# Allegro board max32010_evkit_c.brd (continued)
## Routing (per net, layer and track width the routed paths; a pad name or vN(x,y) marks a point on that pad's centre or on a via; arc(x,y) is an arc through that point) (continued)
UNNAMED_1_RESSMD_I39_2: length 3.8
  TOP w0.356: U1.6 40.71,22.92 41.17,22.45 R4.2
  TOP w0.762: R4.2 43.76,22.45 R5.1
UNNAMED_2_CAPNP_I3_2: length 3.9
  TOP w0.254: R10.2 C13.2 118.24,21.34 118.36,21.46 U4.2
UNNAMED_2_CAPNP_I7_2: length 2.6
  TOP w0.254: U4.1 117.09,22.07 116.84,21.82 C17.2
UNNAMED_2_CAPNP_I18_2: length 2.6
  TOP w0.254: C19.2 116.84,39.6 117.09,39.85 U5.1
UNNAMED_2_CAPNP_I19_2: length 3.9
  TOP w0.254: U5.2 118.36,39.24 118.24,39.12 C14.2 R12.2
UNNAMED_2_CAPNP_I33_2: length 2.8
  TOP w0.254: U7.1 117.13,75.48 116.08,74.42 C23.2
UNNAMED_2_CAPNP_I35_2: length 3.9
  TOP w0.254: U7.2 117.78,75.37 117.47,75.06 C16.2 R16.2
UNNAMED_2_CAPNP_I44_2: length 2.8
  TOP w0.254: C21.2 116.08,56.64 117.13,57.7 U6.1
UNNAMED_2_CAPNP_I46_2: length 3.9
  TOP w0.254: U6.2 117.78,57.59 117.47,57.28 C15.2 R14.2
UNNAMED_2_MAX5322_I51_CLR: length 2.6
  TOP w0.254: U8.6 130.85,19.54 R18.2
UNNAMED_2_MAX5322_I51_SHDN: length 2.5
  TOP w0.254: R19.2 129.55,19.47 U8.4
UNNAMED_2_MAX5322_I73_CLR: length 2.6
  TOP w0.254: R20.2 130.85,37.32 U9.6
UNNAMED_2_MAX5322_I73_SHDN: length 2.5
  TOP w0.254: R21.2 129.55,37.25 U9.4
UNNAMED_2_MAX5322_I92_CLR: length 2.3
  TOP w0.254: U10.6 130.85,55.36 R22.2
UNNAMED_2_MAX5322_I92_SHDN: length 2.3
  TOP w0.254: U10.4 129.55,56.09 129.54,56.08 R23.2
UNNAMED_2_MAX5322_I111_CLR: length 2.6
  TOP w0.254: R24.2 130.85,72.88 U11.6
UNNAMED_2_MAX5322_I111_SHDN: length 2.5
  TOP w0.254: R25.2 129.55,72.81 U11.4
UNNAMED_2_MAX6126_I1_GNDS: length 2.5
  TOP w0.254: R11.1 121.03,21.34 120.9,21.46 U4.4
UNNAMED_2_MAX6126_I13_GNDS: length 2.5
  TOP w0.254: U5.4 120.9,39.24 121.03,39.12 R13.1
UNNAMED_2_MAX6126_I25_GNDS: length 2.9
  TOP w0.254: U6.4 119.09,57.57 120.24,56.41 R15.1
UNNAMED_2_MAX6126_I50_GNDS: length 2.9
  TOP w0.254: R17.1 120.24,74.19 119.09,75.35 U7.4
UNNAMED_2_MAX44245_I130_INA: length 6
  TOP w0.254: R57.2 R59.1 144.06,27.41 144.37,27.72 U14.2
UNNAMED_2_MAX44245_I131_INB: length 6
  TOP w0.254: U14.6 146.97,27.72 147.28,27.41 R58.1 R56.2
UNNAMED_2_MAX44245_I132_INC: length 5.9
  TOP w0.254: R60.2 R62.1 147.35,41.17 146.97,40.8 U14.9
UNNAMED_2_MAX44245_I133_IND: length 5.8
  TOP w0.254: R61.2 R63.1 143.87,41.17 144.37,40.67 U14.13
UNNAMED_5_CAPNP_I49_1: length 19.1
  TOP w0.254: U12.23 68.5,40.47 76.2,32.77 C62.1
UNNAMED_5_CAPNP_I51_1: length 19.5
  TOP w0.254: U12.24 69,40.98 77.6,32.38 C61.1
UNNAMED_5_CAPNP_I147_1: length 20.4
  TOP w0.254: U12.69 60.5,68.28 56.39,72.39 56.39,77.62 56.64,77.88 C60.1
UNNAMED_5_CAPNP_I147_2: length 18.1
  TOP w0.254: C60.2 57.15,72.64 61,68.79 U12.68
UNNAMED_5_CAPNP_I155_2: length 2.2
  TOP w0.254: U15.6 141.18,97.61 C68.2
UNNAMED_5_CAPNP_I158_2: length 3.8
  TOP w0.356: C67.2 147.07,97.43 146.89,97.61 U15.3 144.6,97.61 U15.9
UNNAMED_5_CAPNP_I169_2: length 3.1
  TOP w0.356: C75.2 106.68,53.72 106,53.05 U16.17
UNNAMED_5_CAPNP_I171_2: length 2.8
  TOP w0.356: U16.16 106.71,52.4 C74.2
UNNAMED_5_EKMAX32010_I1_21: length 29.2
  TOP w0.254: U12.21 67.5,40.45 75.44,32.51 75.44,25.1 78.69,21.84 VRXP.1
UNNAMED_5_EKMAX32010_I1_40: length 21
  TOP w0.254: EXTSEL.1 79.76,56.39 76.44,53.07 U12.40
UNNAMED_5_EKMAX32010_I1_41: length 21.9
  TOP w0.254: U12.41 73.38,53.57 v1(73.91,54.1) 74.8,54.1 80.26,59.56 HITEMP.1
  BOTTOM w0.254: v1(73.91,54.1) R47.2 R45.2
UNNAMED_5_EKMAX32010_I1_42: length 25.7
  TOP w0.254: ILIMLO.1 80.52,62.1 v1(73.91,55.5) 72.48,54.07 U12.42
  BOTTOM w0.254: v1(73.91,55.5) R43.2 R44.2
UNNAMED_5_EKMAX32010_I1_43: length 24.8
  TOP w0.254: U12.43 72.08,54.57 73.96,56.46 v1(73.96,58.29) 80.31,64.64 ILIMHI.1
  BOTTOM w0.254: R42.2 R41.2 v1(73.96,58.29)
UNNAMED_5_HEADER2P_I37_2: length 42.4
  TOP w0.254: U12.15 v1(64.5,42.93)
  BOTTOM w0.254: J1.2 55.75,16.76 52.45,20.07 52.45,37.59 58.42,43.56 62.61,43.56 63.25,42.93 v1(64.5,42.93)
UNNAMED_5_HEADER2P_I38_2: length 33
  TOP w0.254: U12.16 65,43.31 65.12,43.18 65.12,41.94 74.8,32.26 74.8,24.89 77.98,21.72 J2.2
UNNAMED_5_HEADER2P_I71_1: length 31.1
  TOP w0.254: J3.1 87.6,51.84 R30.1 ; J3.1 87.6,50.27 R29.2 ; J3.1 81.28,51.05 81.26,51.07 U12.36
  BOTTOM w0.254: VTHR.1 89.03,46.35 88.39,46.99 J3.1
UNNAMED_5_HEADER2P_I160_1: length 110.4
  TOP w0.254: v1(147.07,98.55) 146.77,98.26 U15.4 ; v1(138.56,34.04) J6.1
  BOTTOM w0.254: v1(147.07,98.55) 138.56,90.04 v1(138.56,34.04)
UNNAMED_5_LED_I57_B: length 1.7
  BOTTOM w0.254: R50.1 76.48,42.6 76.59,42.48 DS5.K
UNNAMED_5_LED_I62_B: length 1.7
  BOTTOM w0.254: R48.1 76.48,48.41 76.59,48.53 DS4.K
UNNAMED_5_LED_I83_B: length 25.7
  TOP w0.254: v1(91.57,70.99) 92.2,71.63 DS3.K
  BOTTOM w0.254: R47.1 77.34,54.1 79.88,56.64 79.88,59.31 v1(91.57,70.99)
UNNAMED_5_LED_I91_B: length 25.9
  TOP w0.254: v1(91.69,73.79) 92.32,73.79 92.44,73.91 DS2.K
  BOTTOM w0.254: v1(91.69,73.79) 91.69,72 79.12,59.43 79.12,57.78 78.36,57.02 R44.1
UNNAMED_5_LED_I97_B: length 26
  TOP w0.254: DS1.K v1(91.06,76.2)
  BOTTOM w0.254: R42.1 78.76,59.82 91.06,72.11 v1(91.06,76.2)
VDAC1: length 8.7
  TOP w0.381: U8.21 v1(132.15,27.18) ; U9.21 v1(132.15,44.96)
  BOTTOM w0.508: v1(132.15,27.18) 132.11,27.22 C38.2 C26.2 ; v1(132.15,44.96) 132.11,45 C41.2 C29.2
VDAC2: length 8.7
  TOP w0.381: U10.21 v1(132.15,62.74) ; U11.21 v1(132.15,80.52)
  BOTTOM w0.508: C32.2 C44.2 132.11,62.78 v1(132.15,62.74) ; C35.2 C47.2 132.11,80.56 v1(132.15,80.52)
  vias: v1(40.26,18.92) v1(41.27,18.92) v1(41.27,18.03) v1(110.24,14.1) v1(110.24,12.95) v1(112.01,14.1) v1(112.01,12.95) v1(113.67,14.1) v1(113.67,12.95) v1(115.32,14.1) v1(115.32,12.95)
VL: length 25.2
  TOP w0.254: v1(72.74,51.79) 72.52,51.57 U12.37
  TOP w0.356: U16.14 105.21,51.09 106.78,49.53 C71.2
  TOP w0.508: C71.2 106.4,49.15 105.88,49.15 v1(105.84,49.18)
  TOP w0.635: DS3.A DS2.A DS1.A 95.13,77.33 94.11,78.36 v1(90.81,78.36)
  BOTTOM w0.508: R45.1 v1(77.72,52.7) ; R46.1 v1(77.72,46.23) ; R41.1 v1(77.72,58.29) ; DS4.A 73.85,48.46 v1(73.85,48.45) ; R49.1 v1(77.72,44.83) ; R43.1 v1(77.72,55.5) ; DS5.A v1(73.78,42.04)
VMEAS: length 54.8
  TOP w0.254: v1(73.03,64.26) 74.77,66 90.21,66 94.36,61.85 VMEAS.1 94.36,57.53 93.22,56.39 93.22,53.47 94.11,52.58 96.52,52.58 96.99,53.05 U16.4 ; U12.62 64,58.67 v1(63.5,58.17)
  BOTTOM w0.254: v1(63.5,58.17) 64,58.67 64,62.67 66.1,64.77 72.52,64.77 v1(73.03,64.26)
VTHR: length 5.7
  TOP w0.254: J4.2 TP20.1

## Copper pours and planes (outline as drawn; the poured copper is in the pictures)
+5V on TOP: 19.68,94.36 19.68,98.04 20.07,98.42 37.08,98.42 37.29,98.22 37.29,96.19 37.59,95.89 37.59,93.6 32.89,93.6 29.46,90.17 29.46,88.16 21.46,88.16 21.46,94.36
+5V on INTERNAL3: 34.54,73.15 34.54,101.35 36.83,103.63 48.13,103.63 53.72,98.04 87.88,98.04 91.95,93.98 91.95,52.32 93.09,51.18 127,51.18 127.76,51.94 127.76,80.9 129.03,82.17 132.84,82.17 133.73,81.28 133.73,75.56 131.83,73.66 131.83,52.45 134.49,49.78 145.16,49.78 146.69,48.26 146.69,37.97 145.41,36.7 140.97,36.7 139.19,38.48 131.32,38.48 128.78,35.94 128.78,29.59 130.05,28.32 130.05,25.91 129.54,25.4 122.81,25.4 122.3,25.91 122.3,37.59 121.92,37.97 119.38,37.97 117.47,36.07 117.47,16.76 117.98,16.26 139.19,16.26 140.72,17.78 140.72,30.61 141.6,31.5 150.5,31.5 151.13,32.13 151.13,113.16 1.27,113.16 1.27,72.14 33.53,72.14
GND on TOP: 26.54,52.2 26.54,26.67 25.91,26.04 1.78,26.04 1.27,26.54 1.27,52.2 2.41,53.34 25.4,53.34
GND on BOTTOM: 1.27,113.16 151.13,113.16 151.13,1.27 1.27,1.27 ; 6 cut-outs
GND on INTERNAL2: 1.27,113.16 151.13,113.16 151.13,1.27 1.27,1.27
VCC on TOP: 19.74,19.3 19.74,16.76 24.89,16.76 25.65,16 37.47,16 37.59,16.13 37.59,17.91 37.29,18.21 37.29,21.79 37.72,22.23 37.72,26.16 33.27,26.16 32.77,25.65 32.77,21.84 29.46,21.84 29.46,24.89 26.29,24.89 25.65,24.26 20.95,24.26 20.83,24.13 20.83,20.19 19.94,19.3
VCC on TOP: 54.99,53.85 54.99,57.78 57.66,57.78 57.66,53.85
VCC on INTERNAL3: 56.39,58.67 56.39,46.61 58.29,44.7 69.47,44.7 70.48,45.72 70.48,48.01 68.33,50.16 68.33,52.96 70.1,54.74 70.1,62.36 61.09,71.37 21.72,71.37 21.65,71.31 1.4,71.31 1.4,1.27 151.13,1.27 151.13,30.35 150.62,30.86 142.11,30.86 141.48,30.23 141.48,17.02 139.83,15.37 120.4,15.37 116.71,11.68 36.58,11.68 34.16,14.1 34.16,59.69 35.18,60.71 54.36,60.71
VEE on TOP: 28.68,57.3 19.68,66.29 19.68,81.53 23.37,81.53 23.37,77.98 35.31,77.98 37.08,76.2 37.08,57.3
VEE on TOP: 56.52,53.72 56.52,49.91 53.85,49.91 53.85,53.72
VEE on INTERNAL3: 35.56,59.94 54.1,59.94 55.63,58.42 55.63,45.97 57.4,44.2 69.72,44.2 70.87,45.34 70.87,48.26 69.09,50.04 69.09,52.83 70.61,54.36 70.61,59.69 70.87,59.94 72.64,59.94 73.15,59.44 73.15,57.4 72.01,56.26 72.01,49.91 73.03,48.9 73.03,41.53 73.66,40.89 78.11,40.89 82.17,44.96 106.55,44.96 107.31,45.72 107.31,50.04 107.95,50.67 127.25,50.67 128.27,51.69 128.27,80.64 129.29,81.66 132.46,81.66 133.22,80.9 133.22,75.82 131.44,74.04 131.44,52.07 134.24,49.28 144.91,49.28 146.18,48.01 146.18,38.1 145.29,37.21 141.35,37.21 139.45,39.12 130.94,39.12 128.14,36.32 128.14,29.21 129.41,27.94 129.41,26.16 129.16,25.91 123.19,25.91 122.81,26.29 122.81,37.85 122.05,38.61 119.13,38.61 115.19,34.67 91.82,34.67 86.87,29.72 74.42,29.72 69.47,34.67 36.32,34.67 34.8,36.2 34.8,59.18
DUT_NODE on TOP: 49.91,25.4 49.91,4.57 51.69,2.79 67.94,2.79 72.9,7.75 72.9,29.29 70.56,29.29 70.36,29.08 70.36,27.81 67.94,25.4
DUT_NODE on BOTTOM: 62.48,29.34 67.31,34.16 67.31,43.31 66.04,44.58 63.63,44.58 63.12,45.09 63.12,46.61 63.5,46.99 69.98,46.99 70.74,46.23 70.74,19.68 69.6,18.54 64.14,18.54 55.88,26.8 55.88,29.34
RA on TOP: 61.59,45.09 61.59,43.05 61.09,42.55 61.09,39.88 61.98,38.99 61.98,26.67 45.97,26.67 45.72,26.92 45.72,45.09
RA_O on BOTTOM: 59.69,29.84 59.69,32.13 55.88,32.13 55.88,29.84
UNNAMED_1_BANANA_I1_P on TOP: 20.19,21.72 20.19,20.07 19.86,20.07 19.13,19.33 19.13,16.26 24.26,16.26 25.78,14.73 25.78,2.54 24.51,1.27 10.54,1.27 1.27,1.27 1.27,20.95 2.03,21.72
UNNAMED_1_BANANA_I17_P on TOP: 2.41,83.69 20.19,83.69 20.19,82.17 19.18,82.17 19.18,61.98 2.54,61.98 1.27,63.25 1.27,82.55
UNNAMED_1_BANANA_I26_P on TOP: 25.53,113.16 26.54,112.14 26.54,100.84 24.89,99.19 19.56,99.19 19.18,98.81 19.18,92.96 2.41,92.96 1.27,94.11 1.27,113.16
UNNAMED_1_DIOZENER_I7_A on TOP: 19.13,31.75 19.13,30.61 20.83,30.61 20.83,28.7 18.03,28.7 18.03,31.75
UNNAMED_1_DIOZENER_I14_A on TOP: 19.68,62.87 19.68,61.85 18.03,61.85 18.03,59.82 20.83,59.82 20.83,62.87
UNNAMED_1_DIOZENER_I24_A on TOP: 19.68,93.85 19.68,92.84 18.03,92.84 18.03,90.81 20.83,90.81 20.83,93.85
UNNAMED_1_EVKMAXIMPAD_I8_1 on TOP: 30.23,22.1 30.23,27.05 32.51,27.05 32.51,22.1
UNNAMED_1_EVKMAXIMPAD_I8_1 on BOTTOM: 32.51,22.1 32.51,34.29 29.84,34.29 29.84,22.1
UNNAMED_1_EVKMAXIMPAD_I29_1 on TOP: 30.35,89.92 30.35,85.72 40.77,85.72 41.66,86.61 41.66,89.53 40.77,90.42 30.86,90.42
VDAC1 on TOP: 39.88,23.5 39.88,25.65 39.12,26.42 35.81,26.42 35.81,30.99 40.39,30.99 41.27,30.1 41.27,28.32 41.78,27.81 42.8,27.81 42.8,26.04 42.88,25.96 42.88,24.77 44.32,24.77 44.32,23.5
VDAC1 on BOTTOM: 36.45,33.15 50.16,33.15 51.05,32.26 51.05,19.94 55.88,15.11 90.17,15.11 94.61,10.67 119.13,10.67 122.05,13.59 122.05,43.43 123.19,44.58 130.81,44.58 131.62,45.39 131.62,48.13 132.59,48.13 132.59,43.31 131.06,41.78 128.27,41.78 125.86,39.37 125.86,26.67 126.62,25.91 131.06,25.91 131.62,26.47 131.62,30.23 132.72,30.23 132.72,26.04 128.65,21.97 128.65,10.79 124.08,6.22 93.22,6.22 86.87,12.57 51.56,12.57 46.86,17.27 46.86,25.4 44.7,27.56 36.45,27.56
VDAC2 on TOP: 39.88,17.4 41.4,17.4 41.86,16.94 44.27,16.94 44.27,18.29 42.88,18.29 42.88,19.43 39.88,19.43
VDAC2 on BOTTOM: 131.62,83.57 131.62,80.19 131.06,79.63 112.14,79.63 109.6,77.09 109.6,12.57 110.24,11.94 115.82,11.94 116.46,12.57 116.46,56.52 119.13,59.18 130.43,59.18 132.59,61.34 132.59,65.91 131.62,65.91 131.62,62.66 129.79,60.83 124.08,60.83 123.06,61.85 123.06,72.64 128.02,77.6 131.32,77.6 132.97,79.25 132.97,83.57
VDAC2 on INTERNAL3: 34.8,14.48 34.8,32.51 36.45,34.16 69.34,34.16 74.17,29.34 87,29.34 91.82,34.16 115.32,34.16 116.84,32.64 116.84,12.83 116.33,12.32 36.96,12.32
VL on TOP: 39.88,98.04 39.88,92.2 44.83,92.2 44.83,94.49 43,94.49 43,98.3 41.66,98.3 41.66,102.87 38.48,102.87 38.48,99.44
VL on INTERNAL3: 61.28,72.07 73.66,59.69 73.66,57.15 72.39,55.88 72.39,50.16 73.41,49.15 73.41,41.78 73.79,41.4 78.11,41.4 82.17,45.47 106.55,45.47 106.93,45.85 106.93,50.04 106.3,50.67 92.46,50.67 91.31,51.82 91.31,93.34 87.25,97.41 53.59,97.41 48.01,103 37.08,103 35.18,101.09 35.18,73.28 36.45,72.01 61.21,72.01

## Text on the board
Ref Des/Silkscreen Top: MAX32010_EVKIT_C
User.21: SCAN FOR INFO | KEEP CENTER OF STANDOFF HOLES 0.2" AWAY FROM BOARD EDGES | USE FOR ONLY 1 MAXIM PART OPTION | USE FOR MULTI MAXIM PART OPTIONS | MAXyyyyy_EVKIT_P1 | MAXzzzzz_EVKIT_P1 | THE PLASTIC PRESS-IN STANDOFF (4-PLCS). | DEFAULT MOUNTING HOLE IS FOR | MAXINV# XXXXXX | DEFAULT LOCATION FOR HARDWARE NAME | ADD TEXT UNDER QR CODE | MUST READ "SCAN FOR INFO" | DEFAULT QR CODE LOCATION | DEFAULT LOGO LOCATION | EVKIT NAMING OPTIONS | (HARDWARE NAME ONLY)
User.23: NOTES: | SURFACE FINISH: | TESTING: | SOLDERMASK: | MISCELLANEOUS: | SILKSCREEN: | MATERIAL: | TOOLING: | 16.  VENDOR LOGO & DATE CODE REQUIREMENT.  DATE CODE FORMAT MUST BE YYWW ONLY | 17.  FINAL ELECTRICAL TEST TO BE PERFORMED USING PROVIDED IPC-D-356A NETLIST OR ODB++ FORMAT FILE. | 18.  A TIME DOMAIN REFLECTOMETER REPORT FOR EACH IMPEDANCE CONTROLLED LAYER AND A CERTIFICATE | 19. IF PRESENT, ALL BLIND/BURIED VIAS WITH AN ASPECT RATIO <1:1 TO BE PLATED SHUT WITH COPPER WHEN | 20.  FOR ALL DRILL INFORMATION REFER TO DRILL CHART. | 21.  FINISHED SURFACE CONTACTS AND FILLED VIAS TO BE FREE OF ANY PITS. SCRATCHES PROBE MARKS | 23.  PEMNUT | 14.  SOLDERMASK OVER BARE COPPER OR BARE GOLD (BOTH SIDES) WITH LIQUID PHOTO IMAGEABLE (LPI) INK | 13.  DRILL SIZES ARE FINISHED HOLE SIZES. ALL HOLES SHALL BE LOCATED WITHIN .005 DTP,UNLESS SPECIFIED. | 22.  THIEVING: | 9.  ALL TRACES FILLETED OPTION TO ENHANCE RELIABILITY AT PAD JUNCTIONS | 10.  LAYER TO LAYER REGISTRATIONS SHALL BE WITHIN .003 INCHES. | 15. APPLY SILKSCREEN USING A NON-CONDUCTIVE EPOXY INK | 11.  FINISHED COPPER WEIGHT/THICKNESS: | 12. USE CHECKED ITEMS FOR PLATING | 3.  THE PCB SHALL BE FABRICATED TO IPC-6012, TYPE X, CLASS 2. | 4.  BOARD MATERIAL & CONSTRUCTION SHALL MEET THE REQUIREMENTS OF UL796 | 5.  OVERALL BOARD THICKNESS REFER TO LAMINATION DIAGRAM. TOLERANCE APPLIES | 6.  BOW & TWIST NOT TO EXCEED 0.0075 IN. (0.75%) PER LINEAR INCH. | 7.  PHOTO ETCH CIRCUITRY PER ENCLOSED GERBER RS274X OR ODB++ FORMAT FILE. | 8.  IMPEDANCE REQUIREMENTS: IF NO STACKUP IS DEFINED, THE VENDOR IS ALLOWED TO ADJUST THE DIELECTRIC | 1.  DIMENSIONS ARE IN INCHES (EXCEPT WHERE NOTED). | 2.  BOARD MATERIAL: | (X)  FINISH CONDUCTOR SURFACES: IMMERSION GOLD, 2-5 MICRO INCHES OVER | (X)  WHITE | ( )  OTHER ________________________ | ( )  FINGERS TO BE GOLD PLATED. | (X)  REFER TO LAMINATION DIAGRAM FOR FINISHED COPPER WEIGHT/THICKNESS REQUIREMENTS. | (X)  PLACE ON BOTTOM LEGEND LAYER. IF NO BOTTOM LEGEND SUPPLIED, CREATE BOTTOM LEGEND LAYER TO ADD. | ( )  PLACE ON TOP LEGEND LAYER. IF NO TOP LEGEND SUPPLIED,CREATE TOP LEGEND LAYER TO ADD. | ( )  ELECTRODEPOSITED HARD GOLD PLATE, TYPE 1 (99.7% MIN GOLD), GRADE C | (X)  CUSTOM MAXIM TEAL SOLDER MASK. PANTONE #326C. | MINIMUM BARREL PLATING OF .001 IN. PLATED HOLES SHALL NOT BE ROUGH OR IRREGULAR SO AS TO | HINDER PROPER SOLDER WICKING. BARREL RELIEF ON SOLDERMASK ALLOWED ON UNFILLED VIA IN PAD HOLES. | USED AS VIA-IN PAD OR AS A STACKED VIA. BLIND/BURIED VIAS WITH AN ASPECT RATIO >1:1 TO BE FILLED | WITH NON-CONDUCTIVE EPOXY. UNLESS OTHERWISE SPECIFIED. | ( )  NON-CONDUCTIVE EPOXY. FILL AND CAP ALL 0.XXXX INCH DRILLED VIAS. | ( )  SILVER. FILL AND CAP ALL 0.XXXX INCH DRILLED VIAS. | (REQUIRED UNLESS OTHERWISE SPECIFIED IN QUOTE) | THE PCB SHALL HAVE A VERIFICATION STAMP. | OR OTHER DEFORMITIES THAT COULD EFFECT THE APPERANCE AND PERFORMACE OF THE CONTACT | SURFACE. CONTACTS ARE TO BE AS FLAT AS POSSIBLE. NOT TO EXCEED +/- 0.001" OF FLATNESS. | OF COMPLIANCE SHALL BE PROVIDED BY VENDOR AT TIME OF SHIPMENT. INSTANCES WHERE TDR TESTING | CAN'T BE PERFORMED BECAUSE THE TRACE LENGTH IS TOO SHORT ON THE OUTER LAYERS AT THE PIN ESCAPES | IS ACCEPTABLE, ALL OTHER INSTANCES MUST BE REPORTED. | ( )  SUPPLIER MAY ADD THIEVING TO COMPENSATE FOR LOW COPPER DENSITY AREAS ON THIS DESIGN. | WHERE SPACING PERMITS. | LEGEND TO LEGEND +/- 0.007 INCHES | (X)  SUPPLIER MAY NOT ADD THIEVING TO COMPENSATE FOR LOW COPPER DENSITY AREAS ON THIS DESIGN. | ( )  PEMNUTS TO BE INSTALLED BY FABRICATOR.. | ( )  PEMNUTS NOT TO BE INSTALLED BY FABRICATOR. | (X)  NOT APPLICABLE. | ( )  FILLETED | (X)  NOT FILLETED | (X)  ISOLA 370HR OR EQUIVALENT | ( )  NELCO-4000-13 | ( )  MEGTRON 6 | ( )  ROGERS 4350B | ( )  ROGERS 4003C | ( )  ISOLA-FR408HR OR EQUIVALENT | WORKMANSHIP SHALL CONFORM TO IPC-A-600, CLASS 2, CURRENT REVISIONS. | WITH FLAMMABILITY RATING OF 94V-O. | AFTER ALL LAMINATION AND PLATING PROCESSES. IT IS TO BE MEASURED FROM | TOP PCB METAL TO BOTTOM PCB METAL UNLESS OTHERWISE SPECIFIED. | BOW & TWIST SHOULD BE MEASURED PER IPC-TM-650, METHOD 2.4.22. | DRILL LOCATION AND SIZE CONTROLLED BY EXCELLON CNC DRILL FILE. | THICKNESS AND TRACE WIDTHS TO MEET THE IMPEDANCE REQUIREMENT. IF SPECIFIED, VENDOR MUST FOLLOW AND | MEET THE REQUIREMENTS LISTED IN THE IMPEDANCE TABLE. ANY ADJUSTMENTS MADE TO THE DEFINED STACKUP, | TRACE WIDTH & SPACING THAT IMPACT THE REQUIREMENTS MUST HAVE WRITTEN APPROVAL FROM MAXIM. | UNLESS OTHERWISE SPECIFIED | (USE CHECKED ITEMS FOR MATERIAL) | (KNOOP HARDNESS 130-200), CLASS 1 (50-100 MICRO INCHES THICK) IN ACCORDANCE WITH MIL-G-45204C. | GENERAL SURFACING REQUIREMENTS MUST MEET ANSI/IPC-A-600(CURRENT REV) SECTION 4.0, | CLASS 3 (50-100 MICROINCHES THICK) OVER ELECTRODEPOSITED NICKEL PLATE | IN ACCORDANCE WITH ANSI/IPC-A-600D, SECTION 4.0, CLASS 3 (200-600 MICROINCHES THICK). | 118-236 MICRO INCHES MINIMUM OF ELECTROLESS NICKEL. | THE STARTING COPPER WEIGHT/THICKNESS CAN VARY AS LONG AS THE FINISHED COPPER | WEIGHT/THICKNESS IS NOT LESS THAN THE SPECIFIED VALUE, UNLESS OTHERWISE SPECIFIED. | UNLESS OTHERWISE SPECIFIED: | MAX32010_EVKIT_C
User.45: FIGURE | SIZE | 10.0 | 35.43 | 39.37 | 43.31 | 45.28 | 62.99 | 212.6 | 257.87 | 80.0 | 169.29 | 187.01 | TOLERANCE | +3.0/-8.0 | +3.0/-3.0 | PLATED | NON-PLATED | ALL UNITS ARE IN MILS | QTY | 262 | 6 | 19 | 28 | 22 | 2 | 4 | 8 | NOTES | DRILL CHART: TOP to BOTTOM
